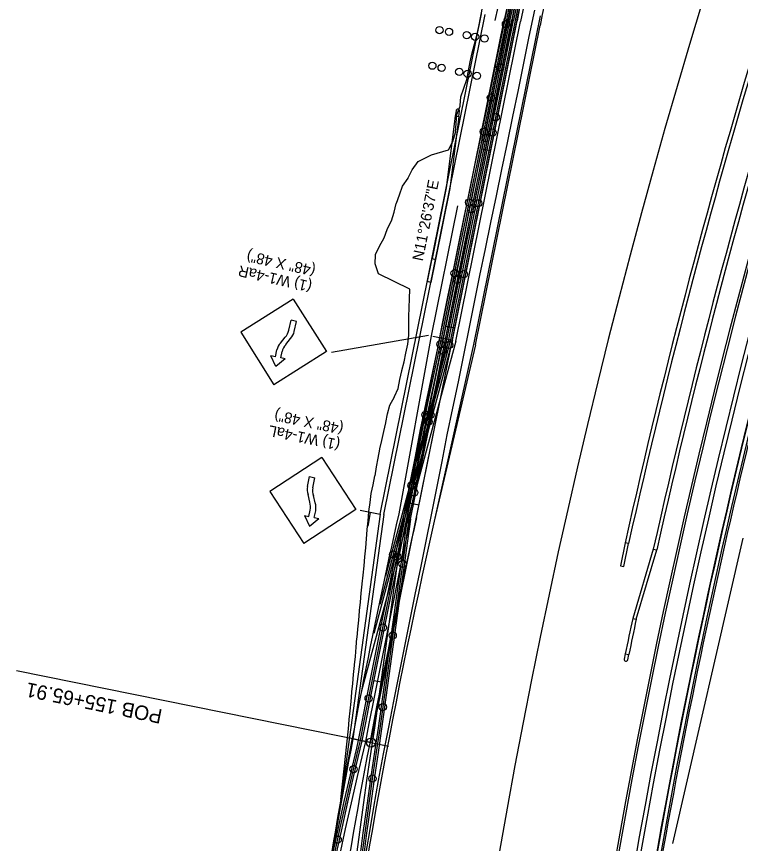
# Model space of a CAD drawing. Extents: x 659657 to 668193, y 633084 to 648639.
# Drawn here: x 661146 to 661546.4, y 640664.4 to 641121.9 of the extents above; entities that cross this region are included whole.
import ezdxf

# ---------------------------------------------------------------- set-up
doc = ezdxf.new("R2010")
doc.units = 0
for name, color, linetype in [('R_Border Prem', 7, 'Continuous'), ('R_MOT_Stage 1A_Striping', 7, 'Continuous'), ('R_MOT_Stage 1C', 7, 'Continuous'), ('R_MOT_Stage 1C_Striping', 7, 'Continuous'), ('R_MOT_Stage 2', 7, 'Continuous'), ('R_MOT_Stage 2_Striping', 7, 'Continuous'), ('R_MOT_Stage 2_Striping_PPM', 7, 'Continuous'), ('R_MOT_Stage 3', 7, 'Continuous'), ('R_MOT_Stage 3_Striping', 7, 'Continuous'), ('R_MOT_Stage 3_Striping_PPM', 7, 'Continuous'), ('R_MOT_Stage 4', 7, 'Continuous'), ('R_MOT_Stage 4_Striping', 7, 'Continuous'), ('R_MOT_Stage 4_Striping_PPM', 7, 'Continuous'), ('R_MOT_Stage 5_Striping_PPM', 7, 'Continuous'), ('R_ROW Annot', 7, 'Continuous'), ('S_EXISTING_ALIGNMENT', 7, 'Continuous'), ('T_Notes', 7, 'Continuous'), ('T_SIGNAL CONTROL CABINET', 7, 'Continuous')]:
    doc.layers.add(name, color=color, linetype=linetype)

msp = doc.modelspace()

# ---------------------------------------------------------------- linework, layer by layer
at = {"layer": 'R_Border Prem'}
msp.add_arc((665219.85, 639999.01), 3863.72, 156.12343, 201.98495, dxfattribs=at)
at = {"layer": 'R_MOT_Stage 1A_Striping'}
msp.add_arc((664800.12, 639948.5), 3293.92, 166.52393, 171.57983, dxfattribs=at)
at = {"layer": 'R_MOT_Stage 1C'}
for radius in [3777.72, 3775.72]:
    msp.add_arc((665219.85, 639999.01), radius, 163.39403, 173.45222, dxfattribs=at)
at = {"layer": 'R_MOT_Stage 1C_Striping'}
for centre, radius, start, end in [((665219.85, 639999.01), 3799.97, 157.70222, 174.95222), ((665219.85, 639999.01), 3788.97, 157.70222, 174.95222), ((665219.85, 639999.01), 3777.97, 163.39302, 174.95222), ((664764.51, 639945.28), 3259.1, 166.3221, 171.43192)]:
    msp.add_arc(centre, radius, start, end, dxfattribs=at)
at = {"layer": 'R_MOT_Stage 2'}
for p, q in [((661498.2, 640827.34), (661486.79, 640788.94)), ((661488.75, 640788.53), (661500.15, 640826.9)), ((661498.2, 640827.34), (661500.15, 640826.9)), ((661486.79, 640788.94), (661488.75, 640788.53)), ((661482.71, 640769.38), (661482.1, 640766.45)), ((661482.71, 640769.38), (661484.67, 640768.98)), ((661484.06, 640766.04), (661484.67, 640768.98))]:
    msp.add_line(p, q, dxfattribs=at)
for points in [[(661401.74, 641116.43), (661409.31, 641155.65), (661412.32, 641170.31)], [(661335.19, 640721.64), (661337.15, 640731.64), (661339.98, 640746.14), (661342.91, 640760.91), (661345.89, 640775.64), (661348.85, 640790.34), (661351.85, 640805.23), (661354.84, 640819.95), (661357.85, 640834.66), (661360.85, 640849.31), (661363.76, 640863.93), (661366.59, 640878.58), (661369.46, 640893.44), (661372.57, 640908.26), (661375.67, 640922.94), (661378.74, 640937.54), (661381.67, 640952.17), (661384.62, 640966.88), (661387.59, 640981.62), (661390.61, 640996.35), (661393.62, 641011), (661396.67, 641025.7), (661399.72, 641040.39), (661402.78, 641055.08), (661405.84, 641069.73), (661408.85, 641084.46), (661411.84, 641099.18), (661414.88, 641113.9), (661417.93, 641128.59)], [(661337.14, 640721.22), (661339.11, 640731.25), (661341.94, 640745.76), (661344.87, 640760.52), (661347.85, 640775.25), (661350.81, 640789.95), (661353.81, 640804.83), (661356.8, 640819.56), (661359.81, 640834.26), (661362.81, 640848.91), (661365.72, 640863.55), (661368.55, 640878.2), (661371.42, 640893.05), (661374.53, 640907.85), (661377.63, 640922.53), (661380.69, 640937.14), (661383.63, 640951.78), (661386.59, 640966.49), (661389.55, 640981.23), (661392.57, 640995.95), (661395.58, 641010.59), (661398.63, 641025.29), (661401.68, 641039.98), (661404.74, 641054.67), (661407.79, 641069.32), (661410.8, 641084.07), (661413.8, 641098.78), (661416.84, 641113.49), (661419.89, 641128.19)], [(661391.76, 641077.49), (661395.07, 641087.03), (661395.09, 641087.12), (661395.98, 641091.98), (661396.94, 641096.89), (661397.99, 641101.78), (661398.01, 641101.87), (661399.25, 641106.64), (661400.53, 641111.48), (661401.72, 641116.34), (661401.74, 641116.43)], [(661389.6, 641067.66), (661391.3, 641072.43), (661391.28, 641072.64), (661391.76, 641077.49)], [(661325.35, 640688.82), (661329.53, 640727.9), (661330, 640732.9), (661330, 640733.01), (661330.49, 640737.9), (661331, 640742.9), (661331.45, 640747.91), (661331.47, 640748.27), (661331.92, 640752.91), (661332.44, 640757.91), (661332.91, 640762.91), (661332.93, 640763.28), (661333.38, 640767.95), (661333.87, 640772.96), (661334.28, 640777.97), (661334.3, 640778.34), (661334.77, 640782.98), (661335.26, 640787.98), (661335.66, 640793.01), (661335.68, 640793.38), (661336.16, 640797.97), (661336.68, 640802.97), (661337.14, 640807.98), (661337.15, 640808.11), (661337.69, 640812.96), (661338.24, 640817.95), (661338.67, 640822.97), (661338.68, 640823.09), (661339.14, 640827.96), (661339.62, 640832.97), (661339.92, 640838.01), (661339.92, 640838.14), (661340.44, 640843), (661340.91, 640848.01), (661341.49, 640852.99), (661341.5, 640853.12), (661342.15, 640858), (661343.21, 640862.89), (661344.22, 640867.78), (661344.25, 640867.91), (661345.08, 640872.72), (661346.06, 640877.62), (661346.95, 640882.54), (661346.98, 640882.7), (661348.01, 640887.42), (661349.06, 640892.31), (661350.15, 640897.19), (661350.18, 640897.34), (661351.15, 640902.07), (661352.36, 640906.92), (661354.98, 640911.5), (661355.06, 640911.64), (661357.01, 640916.19), (661358.04, 640921.09), (661359.06, 640925.98), (661359.09, 640926.14), (661360.33, 640930.82), (661361.35, 640935.72), (661362.38, 640940.61), (661362.42, 640940.76), (661362.91, 640945.61), (661362.98, 640950.69), (661363.05, 640955.78), (661363.05, 640955.93), (661363.23, 640960.84), (661363.36, 640965.91), (661363.49, 640970.99), (661363.5, 640971.14), (661346.23, 640979.57), (661344.39, 640985.04), (661344.53, 640990.11), (661344.48, 640990.27), (661346.78, 640994.83), (661349.31, 640999.42), (661350.97, 641004.19), (661351.02, 641004.32), (661353.36, 641008.84), (661354.76, 641013.65), (661356.01, 641018.5), (661356.06, 641018.71), (661357.73, 641023.33), (661359.51, 641028.07), (661362.54, 641032.55), (661362.63, 641032.75), (661364.89, 641037.2), (661368.08, 641041.64), (661375.22, 641045.27), (661375.54, 641045.42), (661384.93, 641048.26), (661387.3, 641052.88), (661388.76, 641057.69), (661388.83, 641057.89), (661389.6, 641067.66), (661389.6, 641067.66)], [(661305.15, 640568.04), (661308.17, 640584.41), (661310.92, 640598.98), (661313.76, 640613.75), (661316.65, 640628.56), (661319.67, 640643.38), (661322.82, 640658.15), (661326.02, 640672.87), (661329.23, 640687.29), (661332.6, 640702.01), (661336.07, 640716.66), (661337.14, 640721.22)], [(661311.96, 640614.98), (661314.69, 640628.95), (661317.71, 640643.79), (661320.86, 640658.57), (661324.07, 640673.3), (661327.28, 640687.73), (661330.65, 640702.47), (661334.12, 640717.12), (661335.19, 640721.64)]]:
    msp.add_lwpolyline(points, dxfattribs=at)
msp.add_lwpolyline([(661482.58, 640830.81), (661479.97, 640818.08), (661481.93, 640817.68), (661484.53, 640830.38)], close=True, dxfattribs=at)
for centre in [(661416.7, 641117.73), (661385.18, 641113.46), (661395.01, 641111.62), (661404.84, 641109.78), (661381.11, 641093.57), (661390.86, 641091.34), (661400.61, 641089.11), (661408.36, 641077.09), (661404.47, 641058.26), (661396.32, 641019.1), (661388.26, 640979.92), (661380.39, 640940.71), (661372.19, 640901.56), (661364.45, 640862.31), (661356.5, 640823.11), (661348.57, 640783.9), (661340.72, 640744.68), (661332.41, 640705.56), (661323.62, 640666.54)]:
    msp.add_circle(centre, 2, dxfattribs=at)
for centre, radius, start, end in [((665219.85, 639999.01), 3828.72, 162.95222, 167.45222), ((665219.85, 639999.01), 3826.72, 162.95222, 167.45222), ((665219.85, 639999.01), 3812.72, 162.95222, 167.45222), ((665219.85, 639999.01), 3810.72, 162.95222, 167.45222), ((665219.85, 639999.01), 3815.72, 168.05222, 168.35222), ((665219.85, 639999.01), 3813.72, 168.05222, 168.35222), ((661483.08, 640766.24), 1, 168.3522, 348.3522)]:
    msp.add_arc(centre, radius, start, end, dxfattribs=at)
at = {"layer": 'R_MOT_Stage 2_Striping'}
msp.add_line((661341.99, 640720.28), (661462.54, 641315.82), dxfattribs=at)
for points in [[(661339.1, 640720.8), (661341.07, 640730.87), (661343.91, 640745.37), (661346.84, 640760.13), (661349.81, 640774.85), (661352.77, 640789.55), (661355.77, 640804.43), (661358.76, 640819.16), (661361.77, 640833.86), (661364.77, 640848.52), (661367.68, 640863.16), (661370.52, 640877.83), (661373.39, 640892.65), (661376.48, 640907.44), (661379.58, 640922.12), (661382.65, 640936.74), (661385.59, 640951.39), (661388.55, 640966.1), (661391.51, 640980.83), (661394.53, 640995.55), (661397.54, 641010.19), (661400.59, 641024.89), (661403.64, 641039.58), (661406.7, 641054.26), (661409.75, 641068.92), (661412.76, 641083.67), (661415.76, 641098.38), (661418.8, 641113.08), (661421.85, 641127.78)], [(661349.89, 640718.68), (661351.87, 640728.75), (661354.7, 640743.24), (661357.62, 640757.97), (661360.59, 640772.67), (661363.56, 640787.38), (661366.55, 640802.25), (661369.54, 640816.96), (661372.55, 640831.66), (661375.55, 640846.34), (661378.48, 640861.04), (661381.32, 640875.74), (661384.17, 640890.48), (661387.25, 640905.18), (661390.35, 640919.85), (661393.43, 640934.53), (661396.38, 640949.22), (661399.33, 640963.93), (661402.29, 640978.64), (661405.3, 640993.33), (661408.31, 641007.97), (661411.36, 641022.65), (661414.41, 641037.34), (661417.47, 641052.02), (661420.53, 641066.7), (661423.54, 641081.47), (661426.54, 641096.17), (661429.57, 641110.85), (661432.62, 641125.54)], [(661403.37, 641048.72), (661408.28, 641047.73)], [(661383.53, 640950.71), (661388.44, 640949.72)], [(661363.69, 640852.7), (661368.59, 640851.7)], [(661341.99, 640720.28), (661145.97, 640759.96)], [(661343.85, 640754.68), (661348.75, 640753.69)], [(661299.53, 640523.59), (661299.7, 640524.68), (661302.18, 640539.53), (661304.74, 640554.4), (661307.41, 640569.23), (661310.13, 640584.04), (661312.88, 640598.6), (661315.72, 640613.37), (661318.61, 640628.17), (661321.63, 640642.97), (661324.77, 640657.73), (661327.97, 640672.44), (661331.18, 640686.85), (661334.55, 640701.56), (661338.01, 640716.2), (661339.1, 640720.8)], [(661332.19, 640722.26), (661351.79, 640718.3)], [(661332.19, 640722.26), (661351.79, 640718.3)], [(661319.98, 640521.04), (661320.05, 640521.64), (661321.8, 640536.55), (661323.65, 640551.45), (661325.59, 640566.33), (661327.59, 640581.21), (661329.64, 640595.84), (661331.76, 640610.7), (661333.93, 640625.55), (661336.22, 640640.39), (661338.64, 640655.21), (661341.13, 640670.01), (661343.63, 640684.5), (661346.27, 640699.28), (661349.03, 640714.03), (661349.89, 640718.68)]]:
    msp.add_lwpolyline(points, dxfattribs=at)
msp.add_circle((661341.99, 640720.28), 2.5, dxfattribs=at)
at = {"layer": 'R_MOT_Stage 2_Striping_PPM'}
msp.add_line((661508.98, 640664.33), (661547.98, 640833.29), dxfattribs=at)
for centre, radius, start, end in [((665219.85, 639999.01), 3798.72, 158.32294, 176.45222), ((665219.85, 639999.01), 3786.72, 158.32294, 176.45222), ((665219.85, 639999.01), 3774.72, 165.19143, 172.71234), ((664866.31, 640052.27), 3335.18, 168.52205, 177.48815)]:
    msp.add_arc(centre, radius, start, end, dxfattribs=at)
at = {"layer": 'R_MOT_Stage 3'}
for p, q in [((661347.18, 640846.7), (661403.21, 641123.49)), ((661361.97, 640844.18), (661417.91, 641120.52)), ((661389.06, 641069.82), (661388.68, 641066.84)), ((661390.67, 641066.59), (661391.04, 641069.57)), ((661388.68, 641066.85), (661383.7, 641027.12)), ((661390.67, 641066.6), (661385.67, 641026.8)), ((661388.68, 641066.85), (661390.67, 641066.6)), ((661383.7, 641027.12), (661375.78, 640987.99)), ((661385.67, 641026.8), (661377.74, 640987.59)), ((661347.18, 640846.7), (661326.04, 640693.77)), ((661361.97, 640844.18), (661345.94, 640728.2))]:
    msp.add_line(p, q, dxfattribs=at)
msp.add_lwpolyline([(661375.78, 640987.99), (661377.74, 640987.59), (661375.16, 640974.85), (661373.2, 640975.25)], close=True, dxfattribs=at)
msp.add_lwpolyline([(661345.94, 640728.2), (661343.98, 640715.05), (661341.78, 640700.27), (661339.71, 640685.48), (661337.6, 640670.36), (661335.67, 640655.55), (661333.77, 640640.75), (661332.03, 640625.93), (661330.3, 640611.11), (661328.76, 640596.28), (661327.21, 640581.19), (661325.58, 640563.03)], dxfattribs=at)
for centre in [(661413.53, 641093.84), (661405.59, 641054.64), (661397.66, 641015.43), (661389.72, 640976.23), (661381.78, 640937.02), (661373.85, 640897.82), (661365.91, 640858.61), (661359.52, 640819.15), (661354.04, 640779.52), (661348.57, 640739.9), (661342.8, 640700.32)]:
    msp.add_circle(centre, 2, dxfattribs=at)
for centre, radius, start, end in [((662363.66, 640929.07), 964.93, 163.80643, 168.55644), ((661390.05, 641069.7), 1, 352.7957, 172.7957)]:
    msp.add_arc(centre, radius, start, end, dxfattribs=at)
at = {"layer": 'R_MOT_Stage 3_Striping'}
for p, q in [((661341.99, 640720.28), (661462.54, 641315.82)), ((661349.15, 640846.37), (661405.17, 641123.1)), ((661360, 640844.52), (661415.95, 641120.91)), ((661349.15, 640846.37), (661332, 640722.3)), ((661360, 640844.52), (661343.96, 640728.49))]:
    msp.add_line(p, q, dxfattribs=at)
for points in [[(661403.37, 641048.72), (661408.28, 641047.73)], [(661383.53, 640950.71), (661388.44, 640949.72)], [(661363.69, 640852.7), (661368.59, 640851.7)], [(661341.99, 640720.28), (661145.97, 640759.96)], [(661343.85, 640754.68), (661348.75, 640753.69)], [(661343.96, 640728.49), (661342, 640715.34), (661339.8, 640700.56), (661337.73, 640685.75), (661335.62, 640670.63), (661333.69, 640655.8), (661331.78, 640640.99), (661330.04, 640626.16), (661328.31, 640611.33), (661326.77, 640596.49), (661325.22, 640581.38), (661323.89, 640566.51), (661322.56, 640551.6), (661321.31, 640536.69), (661320.06, 640521.76), (661320.04, 640521.47)], [(661332.19, 640722.26), (661351.79, 640718.3)], [(661332.19, 640722.26), (661351.79, 640718.3)]]:
    msp.add_lwpolyline(points, dxfattribs=at)
msp.add_circle((661341.99, 640720.28), 2.5, dxfattribs=at)
for centre, radius, start, end in [((662363.66, 640929.07), 966.93, 163.80871, 168.55644), ((664934.73, 640031.5), 3668.36, 169.14567, 172.29086)]:
    msp.add_arc(centre, radius, start, end, dxfattribs=at)
at = {"layer": 'R_MOT_Stage 3_Striping_PPM'}
msp.add_line((661508.98, 640664.33), (661547.98, 640833.29), dxfattribs=at)
for centre, radius, start, end in [((665219.85, 639999.01), 3798.72, 158.32294, 176.45222), ((665219.85, 639999.01), 3786.72, 158.32294, 176.45222), ((665219.85, 639999.01), 3774.72, 165.19143, 172.71234), ((664866.31, 640052.27), 3335.18, 168.52205, 177.48815)]:
    msp.add_arc(centre, radius, start, end, dxfattribs=at)
at = {"layer": 'R_MOT_Stage 4'}
for p, q in [((661385.1, 640943.33), (661420.85, 641119.92)), ((661387.05, 640942.88), (661422.81, 641119.53)), ((661387.05, 640942.88), (661343.69, 640780.55)), ((661385.1, 640943.33), (661350.11, 640812.33))]:
    msp.add_line(p, q, dxfattribs=at)
for centre in [(661379.95, 641114.44), (661399.61, 641110.76), (661375.97, 641094.74), (661395.47, 641090.29), (661411, 641066.23), (661409.29, 641057.79), (661401.36, 641018.59), (661393.42, 640979.38), (661385.31, 640940.22), (661374.98, 640901.57), (661364.66, 640862.93), (661354.33, 640824.28)]:
    msp.add_circle(centre, 2, dxfattribs=at)
for radius in [961.93, 959.93]:
    msp.add_arc((662363.66, 640929.07), radius, 156.60619, 168.55644, dxfattribs=at)
at = {"layer": 'R_MOT_Stage 4_Striping'}
for p, q in [((661389, 640942.42), (661424.77, 641119.13)), ((661399.78, 640940.24), (661435.55, 641116.95)), ((661389, 640942.42), (661336.71, 640748.94)), ((661399.78, 640940.24), (661377, 640842.82))]:
    msp.add_line(p, q, dxfattribs=at)
for radius in [957.93, 946.93]:
    msp.add_arc((662363.66, 640929.07), radius, 156.60619, 168.55644, dxfattribs=at)
at = {"layer": 'R_MOT_Stage 4_Striping_PPM'}
msp.add_line((661508.98, 640664.33), (661547.98, 640833.29), dxfattribs=at)
for centre, radius, start, end in [((665219.85, 639999.01), 3798.72, 158.32294, 176.45222), ((665219.85, 639999.01), 3786.72, 158.32294, 176.45222), ((665219.85, 639999.01), 3774.72, 165.19143, 172.71234), ((664936.08, 640039.23), 3648.67, 167.27675, 172.4107), ((664936.08, 640039.23), 3668.67, 168.84564, 172.41325), ((664936.08, 640039.23), 3658.67, 168.84564, 172.41198), ((664866.31, 640052.27), 3335.18, 168.52205, 177.48815)]:
    msp.add_arc(centre, radius, start, end, dxfattribs=at)
at = {"layer": 'R_MOT_Stage 5_Striping_PPM'}
for p, q in [((661367.2, 640844.8), (661423.87, 641124.77)), ((661412.11, 641127.15), (661410.6, 641119.68)), ((661389.85, 641017.19), (661375.28, 640945.2)), ((661375.28, 640945.2), (661357.4, 640846.79)), ((661508.98, 640664.33), (661547.98, 640833.29))]:
    msp.add_line(p, q, dxfattribs=at)
msp.add_lwpolyline([(661435.63, 641122.39), (661398.8, 640940.44), (661377, 640842.82)], dxfattribs=at)
for centre, radius, start, end in [((665219.85, 639999.01), 3798.72, 158.32294, 176.45222), ((665219.85, 639999.01), 3786.72, 158.32294, 176.45222), ((665219.85, 639999.01), 3774.72, 165.19143, 172.71234), ((664936.08, 640039.23), 3668.67, 167.28372, 168.84564), ((664936.08, 640039.23), 3658.67, 167.28024, 168.84564), ((664936.08, 640039.23), 3648.67, 167.27675, 172.4107), ((664936.08, 640039.23), 3668.67, 168.84564, 172.41325), ((664936.08, 640039.23), 3658.67, 168.84564, 172.41198), ((664866.31, 640052.27), 3335.18, 168.52205, 177.48815)]:
    msp.add_arc(centre, radius, start, end, dxfattribs=at)
at = {"layer": 'R_ROW Annot'}
for p, q in [((661299.06, 640965.61), (661270, 640947.25)), ((661299.06, 640965.61), (661317.41, 640936.56)), ((661296.62, 640948.37), (661297.87, 640953.92)), ((661300.82, 640953.25), (661297.87, 640953.92)), ((661299.57, 640947.71), (661300.82, 640953.25)), ((661270, 640947.25), (661288.36, 640918.19)), ((661292.04, 640941.31), (661294.52, 640944.53)), ((661373.8, 640945.41), (661320.11, 640936.11)), ((661376.27, 640945.06), (661387.3, 640942.83)), ((661294.84, 640940.46), (661297.47, 640943.86)), ((661381.72, 640943.79), (661380.2, 640936.26)), ((661317.41, 640936.56), (661288.36, 640918.19)), ((661289.12, 640933.72), (661289.97, 640937.46)), ((661292.07, 640933.05), (661292.86, 640936.55)), ((661289.12, 640933.72), (661286.67, 640934.27)), ((661289.45, 640928.28), (661286.67, 640934.27)), ((661294.53, 640932.5), (661289.45, 640928.28)), ((661294.53, 640932.5), (661292.07, 640933.05))]:
    msp.add_line(p, q, dxfattribs=at)
for centre, start, end in [((661289.21, 640949.86), 314.8585, 348.6164), ((661292.19, 640949.19), 314.8585, 348.6164), ((661297.34, 640935.98), 134.8585, 168.6164), ((661300.24, 640935.06), 134.8585, 168.6164)]:
    msp.add_arc(centre, 7.52, start, end, dxfattribs=at)
at = {"layer": 'S_EXISTING_ALIGNMENT'}
msp.add_line((661341.99, 640720.28), (661462.54, 641315.82), dxfattribs=at)
at = {"layer": 'T_Notes'}
for p, q in [((661314.79, 640877.94), (661286.07, 640859.07)), ((661314.79, 640877.94), (661333.65, 640849.2)), ((661306.92, 640861.84), (661308.08, 640867.41)), ((661308.08, 640867.41), (661311.03, 640866.8)), ((661309.88, 640861.23), (661311.03, 640866.8)), ((661286.07, 640859.07), (661304.91, 640830.33)), ((661308.23, 640853.29), (661307.24, 640857.48)), ((661311.14, 640852.91), (661310.2, 640856.86)), ((661333.65, 640849.2), (661304.91, 640830.33)), ((661307.69, 640845.4), (661308.42, 640848.91)), ((661310.65, 640844.79), (661311.43, 640848.55)), ((661336.11, 640848.74), (661347.18, 640846.7)), ((661305.22, 640845.91), (661308.1, 640839.97)), ((661305.22, 640845.91), (661307.69, 640845.4)), ((661308.1, 640839.97), (661313.11, 640844.28)), ((661310.65, 640844.79), (661313.11, 640844.28)), ((661341.59, 640847.57), (661340.19, 640840.02))]:
    msp.add_line(p, q, dxfattribs=at)
for centre, start, end in [((661314.25, 640860.15), 166.9552, 200.7131), ((661317.24, 640859.53), 166.9552, 200.7131), ((661301.09, 640850.61), 346.9552, 20.7131), ((661304.1, 640850.25), 346.9552, 20.7131)]:
    msp.add_arc(centre, 7.52, start, end, dxfattribs=at)
at = {"layer": 'T_SIGNAL CONTROL CABINET'}
for p, q in [((661418.89, 641120.32), (661362.96, 640844.02)), ((661363.94, 640843.85), (661419.87, 641120.12)), ((661421.83, 641119.72), (661386.08, 640943.11)), ((661386.08, 640943.11), (661346.97, 640796.71)), ((661362.96, 640844.02), (661346.93, 640728.06)), ((661363.94, 640843.85), (661347.92, 640727.92))]:
    msp.add_line(p, q, dxfattribs=at)
for points in [[(661336.17, 640721.43), (661338.13, 640731.44), (661340.96, 640745.95), (661343.89, 640760.71), (661346.87, 640775.44), (661349.83, 640790.14), (661352.83, 640805.03), (661355.82, 640819.75), (661358.83, 640834.46), (661361.83, 640849.11), (661364.74, 640863.74), (661367.57, 640878.39), (661370.44, 640893.24), (661373.55, 640908.06), (661376.65, 640922.74), (661379.72, 640937.34), (661382.65, 640951.98), (661385.6, 640966.69), (661388.57, 640981.42), (661391.59, 640996.15), (661394.6, 641010.8), (661397.65, 641025.5), (661400.7, 641040.19), (661403.76, 641054.87), (661406.81, 641069.52), (661409.83, 641084.26), (661412.82, 641098.98), (661415.86, 641113.69), (661418.91, 641128.39)], [(661346.93, 640728.06), (661344.97, 640714.9), (661342.77, 640700.13), (661340.7, 640685.34), (661338.59, 640670.23), (661336.67, 640655.42), (661334.76, 640640.62), (661333.02, 640625.81), (661331.3, 640611), (661329.75, 640596.18), (661328.23, 640581.38)], [(661347.92, 640727.92), (661345.96, 640714.76), (661343.76, 640699.99), (661341.69, 640685.2), (661339.58, 640670.09), (661337.66, 640655.29), (661335.75, 640640.5), (661334.01, 640625.7), (661332.29, 640610.9), (661331.41, 640602.44)], [(661307.85, 640588.11), (661309.94, 640599.17), (661312.78, 640613.95), (661315.67, 640628.75), (661318.69, 640643.58), (661321.84, 640658.36), (661325.04, 640673.09), (661328.25, 640687.51), (661331.63, 640702.24), (661335.09, 640716.89), (661336.17, 640721.43)]]:
    msp.add_lwpolyline(points, dxfattribs=at)
for radius, start in [(960.93, 156.60619), (963.93, 163.80529), (962.93, 163.80415)]:
    msp.add_arc((662363.66, 640929.07), radius, start, 168.55644, dxfattribs=at)

# ---------------------------------------------------------------- texts
at = {"layer": 'R_MOT_Stage 2_Striping'}
for s, height, rotation, p in [('N11%%d26\'37"E', 6, 78.5564, (661370.65, 640986.33)), ('POB 155+65.91', 8, 168.5564, (661227.06, 640738.44))]:
    msp.add_text(s, height=height, rotation=rotation, dxfattribs=at).set_placement(p)
at = {"layer": 'R_MOT_Stage 3_Striping'}
for s, height, rotation, p in [('N11%%d26\'37"E', 6, 78.5564, (661370.65, 640986.33)), ('POB 155+65.91', 8, 168.5564, (661227.06, 640738.44))]:
    msp.add_text(s, height=height, rotation=rotation, dxfattribs=at).set_placement(p)
at = {"layer": 'R_ROW Annot'}
for s, p in [('(48" X 48")', (661311.75, 640983.96)), ('(1) W1-4aR', (661309.77, 640975.18))]:
    msp.add_text(s, height=6, rotation=167.2914, dxfattribs=at).set_placement(p)
at = {"layer": 'T_Notes'}
for s, p in [('(48" X 48")', (661327.17, 640896.5)), ('(1) W1-4aL', (661325.34, 640887.69))]:
    msp.add_text(s, height=6, rotation=168.2802, dxfattribs=at).set_placement(p)

doc.saveas('drawing.dxf')
